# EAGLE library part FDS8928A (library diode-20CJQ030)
Fairchild's FDS8928A Dual N & P-Channel Enhancement Mode Field Effect Transistor General Description: These dual N- and P -Channel enhancement mode power field effect transistors are produced using Fairchild's proprietary, high cell density, DMOS technology. This very high density process is especially tailored to minimize on-state resistance and provide superior switching performance. These devices are particularly suited for low voltage applications such as notebook computer power management and other battery powered circuits where fast switching, low in-line power loss, and resistance to transients are needed. Features: N-Channel 5.5 A,30 V, RDS(ON)=0.030 W @ VGS=4.5 V RDS(ON)=0.038 W @ VGS=2.5 V. P-Channel -4 A,-20 V, RDS(ON)=0.055 W @ VGS=-4.5 V RDS(ON)=0.072 W @ VGS=-2.5 V. High density cell design for extremely low RDS(ON). High power and current handling capability in a widely used surface mount package. Dual (N & P-Channel) MOSFET in surface mount package. Please send any comments to: messi@users.sourceforge.net
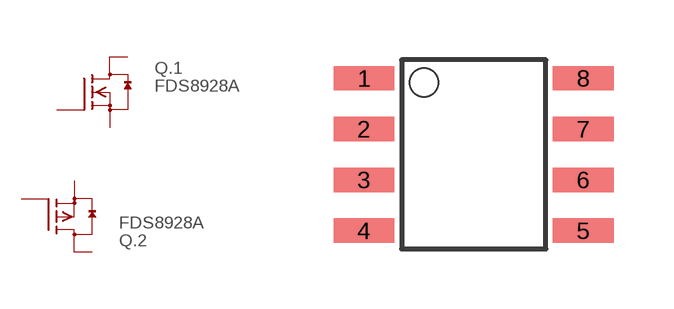
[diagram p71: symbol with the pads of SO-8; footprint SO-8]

Designator prefix Q; gates .1=IGFET-4-N-CH .2=IGFET-4-P-CH

## FDS8928A  [SO-8]
1  .1:S  pas
2  .1:G  pas
3  .2:S  pas
4  .2:G  pas
5  .2:D  pas
6  .2:D  pas
7  .1:D  pas
8  .1:D  pas

## Footprint SO-8 (pad centres in mm)
small outline
smd 1.524 x 0.61: 1 -2.743,1.27; 2 -2.743,0; 3 -2.743,-1.27; 4 -2.743,-2.54; 5 2.743,-2.54; 6 2.743,-1.27; 7 2.743,0; 8 2.743,1.27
